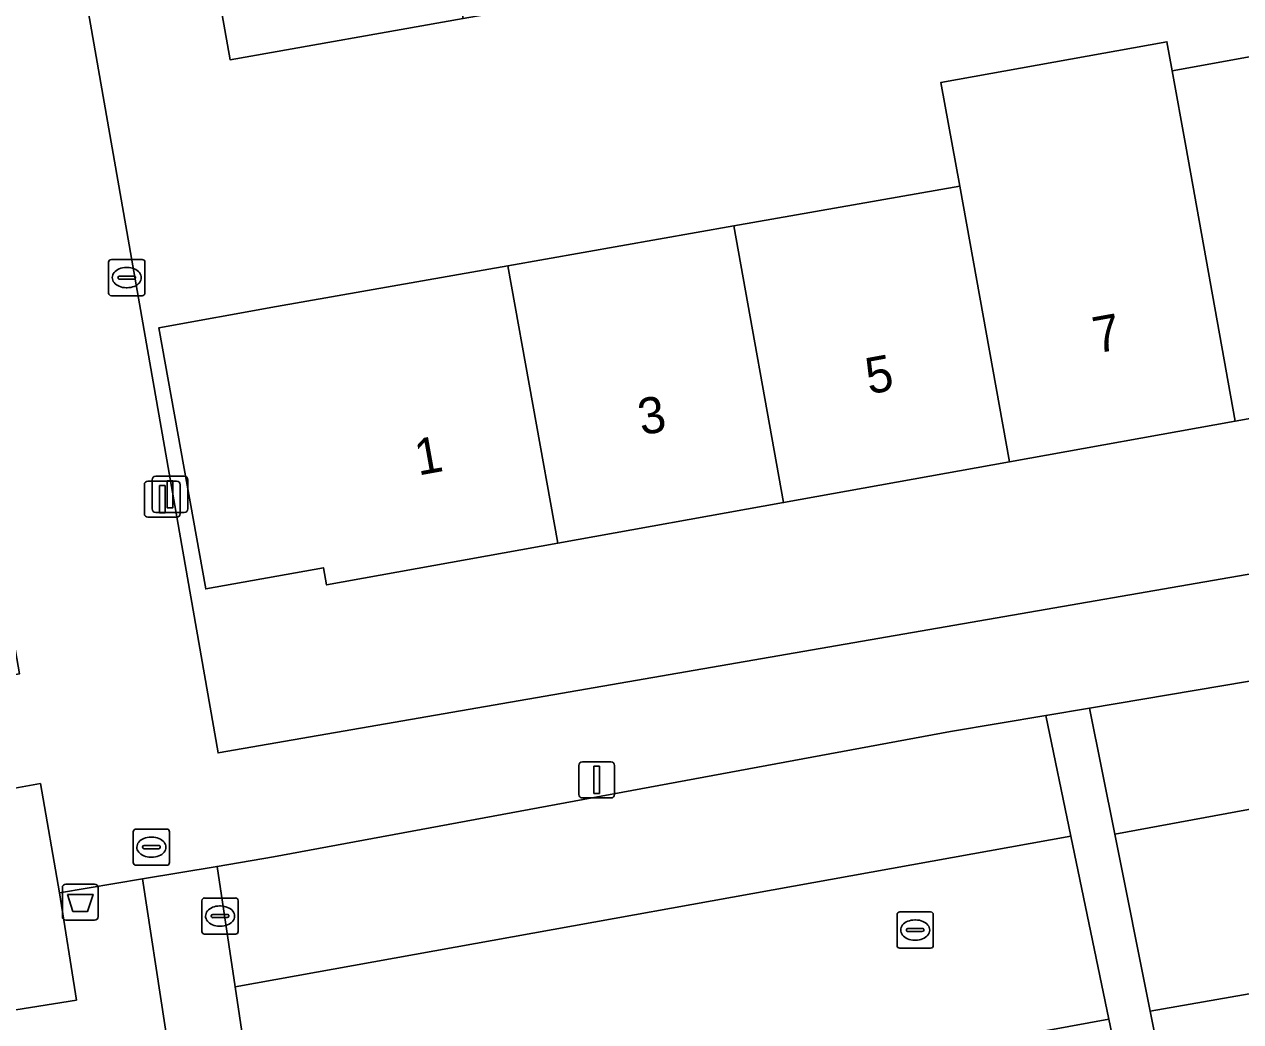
# Model space of a CAD drawing. Extents: x 162879 to 165540, y 384011 to 385181.
# Drawn here: x 164301.67 to 164335.25, y 384254.15 to 384281.7 of the extents above; entities that cross this region are included whole.
import ezdxf

# ---------------------------------------------------------------- set-up
doc = ezdxf.new("R2010")
doc.units = 0
for name, color, linetype in [('IMGEO_Afvalbak', 7, 'Continuous'), ('IMGEO_Erf', 7, 'Continuous'), ('IMGEO_Groenvoorziening', 7, 'Continuous'), ('IMGEO_Kolk', 7, 'Continuous'), ('IMGEO_Lichtmast', 7, 'Continuous'), ('IMGEO_Pand', 7, 'Continuous'), ('IMGEO_Pand_nummerreeks', 7, 'Continuous'), ('IMGEO_Rioolput', 7, 'Continuous'), ('IMGEO_Voetpad_open', 7, 'Continuous')]:
    doc.layers.add(name, color=color, linetype=linetype)

msp = doc.modelspace()

# ---------------------------------------------------------------- linework, layer by layer
at = {"layer": 'IMGEO_Afvalbak'}
for p, q in [((164302.817, 384257.951), (164303.607, 384257.951)), ((164303.607, 384257.951), (164302.817, 384257.951)), ((164302.717, 384257.051), (164302.717, 384257.851)), ((164302.717, 384257.851), (164302.717, 384257.051)), ((164303.707, 384257.851), (164303.707, 384257.051)), ((164303.707, 384257.051), (164303.707, 384257.851)), ((164303.607, 384256.951), (164302.817, 384256.951)), ((164302.817, 384256.951), (164303.607, 384256.951))]:
    msp.add_line(p, q, dxfattribs=at)
msp.add_lwpolyline([(164302.86, 384257.665), (164303.564, 384257.665), (164303.415, 384257.195), (164303.009, 384257.195), (164302.86, 384257.665)], dxfattribs=at)
for centre, start, end in [((164302.817, 384257.851), 90, 180), ((164302.817, 384257.851), 90, 180), ((164303.607, 384257.851), 0, 90), ((164303.607, 384257.851), 360, 90), ((164302.817, 384257.051), 180, 270), ((164302.817, 384257.051), 180, 270), ((164303.607, 384257.051), 270, 0), ((164303.607, 384257.051), 270, 0)]:
    msp.add_arc(centre, 0.1, start, end, dxfattribs=at)
at = {"layer": 'IMGEO_Erf'}
for points in [[(164335.398, 384291.845), (164328.093, 384290.555), (164329.15, 384284.573), (164326.262, 384284.063), (164320.023, 384282.961), (164313.783, 384281.859), (164307.35, 384280.723), (164306.453, 384285.806), (164302.892, 384285.13), (164307.016, 384261.573), (164356.192, 384270.104)], [(164341.337, 384271.862), (164335.102, 384270.739), (164328.866, 384269.615), (164322.631, 384268.491), (164316.395, 384267.367), (164310.011, 384266.217), (164309.926, 384266.689), (164306.678, 384266.104), (164305.378, 384273.317), (164308.626, 384273.902), (164315.014, 384275.029), (164321.254, 384276.131), (164327.493, 384277.232), (164326.976, 384280.098), (164333.212, 384281.222), (164333.357, 384280.421), (164339.591, 384281.545)]]:
    msp.add_lwpolyline(points, dxfattribs=at)
at = {"layer": 'IMGEO_Groenvoorziening'}
for points in [[(164444.217, 384277.406), (164432.573, 384275.206), (164431.046, 384274.979), (164412.171, 384271.782), (164411.664, 384273.084), (164410.216, 384273.782), (164408.706, 384273.531), (164371.45, 384267.278), (164359.532, 384265.161), (164358.499, 384264.978), (164354.911, 384264.392), (164355.011, 384263.622), (164331.775, 384259.327), (164332.753, 384254.442), (164367.352, 384260.503), (164371.077, 384261.125), (164385.399, 384263.612), (164397.49, 384266.196), (164412.669, 384268.778), (164431.26, 384272.662), (164431.272, 384272.664), (164433.193, 384273.044), (164448.321, 384276.269)], [(164448.321, 384276.269), (164433.193, 384273.044), (164431.272, 384272.664), (164431.26, 384272.662), (164412.669, 384268.778), (164397.49, 384266.196), (164385.399, 384263.612), (164371.077, 384261.125), (164367.352, 384260.503), (164332.753, 384254.442), (164333.391, 384251.229), (164332.291, 384250.966), (164331.608, 384254.221), (164308.265, 384249.94), (164308.753, 384246.272), (164306.778, 384245.994), (164298.825, 384244.409), (164297.191, 384244.242), (164295.55, 384244.131), (164274.277, 384245.855), (164270.872, 384246.664), (164271.625, 384245.117)]]:
    msp.add_lwpolyline(points, dxfattribs=at)
for points in [[(164354.911, 384264.392), (164358.499, 384264.978), (164359.532, 384265.161), (164359.516, 384265.186), (164359.415, 384265.343), (164357.5, 384268.334), (164354.177, 384267.752), (164354.364, 384266.743), (164331.078, 384262.811), (164331.775, 384259.327), (164355.011, 384263.622)], [(164329.87, 384262.607), (164327.238, 384262.163), (164308.547, 384258.7), (164306.991, 384258.44), (164307.49, 384255.113), (164330.56, 384259.276)], [(164302.642, 384257.713), (164302.113, 384260.729), (164300.487, 384260.439), (164279.706, 384256.863), (164269.622, 384255.082), (164267.887, 384252.404), (164269.16, 384250), (164269.486, 384249.384), (164303.107, 384254.747)], [(164330.56, 384259.276), (164307.49, 384255.113), (164308.265, 384249.94), (164331.608, 384254.221)], [(164307.49, 384255.113), (164306.991, 384258.44), (164304.926, 384258.095), (164306.778, 384245.994), (164308.753, 384246.272), (164308.265, 384249.94)], [(164304.926, 384258.095), (164302.642, 384257.713), (164303.107, 384254.747), (164269.486, 384249.384), (164270.268, 384247.906), (164270.872, 384246.664), (164274.277, 384245.855), (164295.55, 384244.131), (164297.191, 384244.242), (164298.825, 384244.409), (164306.778, 384245.994)]]:
    msp.add_lwpolyline(points, close=True, dxfattribs=at)
at = {"layer": 'IMGEO_Kolk'}
for p, q in [((164303.995, 384274.279), (164303.995, 384275.131)), ((164304.07, 384275.205), (164304.922, 384275.205)), ((164304.996, 384275.131), (164304.996, 384274.279)), ((164304.254, 384274.699), (164304.254, 384274.711)), ((164304.297, 384274.748), (164304.695, 384274.748)), ((164304.483, 384274.985), (164304.508, 384274.985)), ((164304.738, 384274.711), (164304.738, 384274.699)), ((164304.692, 384274.662), (164304.294, 384274.662)), ((164304.506, 384274.425), (164304.481, 384274.425)), ((164304.922, 384274.205), (164304.07, 384274.205))]:
    msp.add_line(p, q, dxfattribs=at)
for points in [[(164303.995, 384274.279), (164303.995, 384275.131)], [(164304.07, 384275.205), (164304.922, 384275.205)], [(164304.996, 384275.131), (164304.996, 384274.279)], [(164304.922, 384274.205), (164304.07, 384274.205)]]:
    msp.add_lwpolyline(points, dxfattribs=at)
for centre, radius, start, end in [((164304.072, 384275.129), 0.0765, 91.552, 178.448), ((164304.072, 384275.129), 0.0765, 91.552, 178.448), ((164304.92, 384275.129), 0.0765, 1.552, 88.448), ((164304.92, 384275.129), 0.0765, 1.552, 88.448), ((164304.294, 384274.708), 0.0403, 85.8775, 175.7526), ((164304.291, 384274.698), 0.0366, 178.938, 274.7102), ((164304.695, 384274.705), 0.043, 264.8664, 352.4533), ((164304.699, 384274.71), 0.0386, 1.7309, 96.639), ((164304.072, 384274.281), 0.0765, 181.552, 268.448), ((164304.072, 384274.281), 0.0765, 181.552, 268.448), ((164304.92, 384274.281), 0.0765, 271.552, 358.448), ((164304.92, 384274.281), 0.0765, 271.552, 358.448)]:
    msp.add_arc(centre, radius, start, end, dxfattribs=at)
for centre, major_axis, ratio, start_param, end_param in [((164304.482, 384274.705), (-0.387, 0.002), 0.722429, 4.712389, 7.853982), ((164304.507, 384274.705), (-0.39, 0.002), 0.717154, 1.570796, 4.712389)]:
    msp.add_ellipse(centre, major_axis=major_axis, ratio=ratio, start_param=start_param, end_param=end_param, dxfattribs=at)
at = {"layer": 'IMGEO_Lichtmast'}
for p, q in [((164304.982, 384268.184), (164304.982, 384268.984)), ((164304.982, 384268.984), (164304.982, 384268.184)), ((164305.082, 384269.084), (164305.872, 384269.084)), ((164305.872, 384269.084), (164305.082, 384269.084)), ((164305.195, 384268.318), (164305.195, 384269.118)), ((164305.195, 384269.118), (164305.195, 384268.318)), ((164305.295, 384269.218), (164306.085, 384269.218)), ((164306.085, 384269.218), (164305.295, 384269.218)), ((164305.972, 384268.984), (164305.972, 384268.184)), ((164305.972, 384268.184), (164305.972, 384268.984)), ((164306.185, 384269.118), (164306.185, 384268.318)), ((164306.185, 384268.318), (164306.185, 384269.118)), ((164305.872, 384268.084), (164305.082, 384268.084)), ((164305.082, 384268.084), (164305.872, 384268.084)), ((164306.085, 384268.218), (164305.295, 384268.218)), ((164305.295, 384268.218), (164306.085, 384268.218)), ((164317.074, 384261.329), (164317.864, 384261.329)), ((164317.864, 384261.329), (164317.074, 384261.329)), ((164316.974, 384260.429), (164316.974, 384261.229)), ((164316.974, 384261.229), (164316.974, 384260.429)), ((164317.964, 384261.229), (164317.964, 384260.429)), ((164317.964, 384260.429), (164317.964, 384261.229)), ((164317.864, 384260.329), (164317.074, 384260.329)), ((164317.074, 384260.329), (164317.864, 384260.329))]:
    msp.add_line(p, q, dxfattribs=at)
for points in [[(164305.615, 384269.093), (164305.765, 384269.093), (164305.765, 384268.343), (164305.615, 384268.343), (164305.615, 384269.093)], [(164305.402, 384268.959), (164305.552, 384268.959), (164305.552, 384268.209), (164305.402, 384268.209), (164305.402, 384268.959)], [(164317.394, 384261.204), (164317.544, 384261.204), (164317.544, 384260.454), (164317.394, 384260.454), (164317.394, 384261.204)]]:
    msp.add_lwpolyline(points, dxfattribs=at)
for centre, start, end in [((164305.082, 384268.984), 90, 180), ((164305.082, 384268.984), 90, 180), ((164305.295, 384269.118), 90, 180), ((164305.295, 384269.118), 90, 180), ((164305.872, 384268.984), 0, 90), ((164305.872, 384268.984), 360, 90), ((164306.085, 384269.118), 0, 90), ((164306.085, 384269.118), 360, 90), ((164305.295, 384268.318), 180, 270), ((164305.295, 384268.318), 180, 270), ((164306.085, 384268.318), 270, 0), ((164306.085, 384268.318), 270, 0), ((164305.082, 384268.184), 180, 270), ((164305.082, 384268.184), 180, 270), ((164305.872, 384268.184), 270, 0), ((164305.872, 384268.184), 270, 0), ((164317.074, 384261.229), 90, 180), ((164317.074, 384261.229), 90, 180), ((164317.864, 384261.229), 0, 90), ((164317.864, 384261.229), 360, 90), ((164317.074, 384260.429), 180, 270), ((164317.074, 384260.429), 180, 270), ((164317.864, 384260.429), 270, 0), ((164317.864, 384260.429), 270, 0)]:
    msp.add_arc(centre, 0.1, start, end, dxfattribs=at)
at = {"layer": 'IMGEO_Pand'}
for points in [[(164312.705, 384287.837), (164306.294, 384286.705), (164306.453, 384285.806), (164307.35, 384280.723), (164313.783, 384281.859)], [(164339.972, 384279.434), (164339.591, 384281.545), (164333.357, 384280.421), (164333.733, 384278.333), (164335.102, 384270.739), (164341.337, 384271.862)], [(164333.733, 384278.333), (164333.357, 384280.421), (164333.212, 384281.222), (164326.976, 384280.098), (164327.493, 384277.232), (164328.866, 384269.615), (164335.102, 384270.739)], [(164328.866, 384269.615), (164327.493, 384277.232), (164321.254, 384276.131), (164322.631, 384268.491)], [(164322.631, 384268.491), (164321.254, 384276.131), (164315.014, 384275.029), (164316.395, 384267.367)], [(164315.014, 384275.029), (164308.626, 384273.902), (164305.378, 384273.317), (164306.678, 384266.104), (164309.926, 384266.689), (164310.011, 384266.217), (164316.395, 384267.367)]]:
    msp.add_lwpolyline(points, close=True, dxfattribs=at)
at = {"layer": 'IMGEO_Rioolput'}
for p, q in [((164304.675, 384258.545), (164304.675, 384259.397)), ((164304.75, 384259.471), (164305.602, 384259.471)), ((164305.163, 384259.251), (164305.188, 384259.251)), ((164305.676, 384259.397), (164305.676, 384258.545)), ((164304.934, 384258.965), (164304.934, 384258.977)), ((164305.372, 384258.928), (164304.974, 384258.928)), ((164304.977, 384259.014), (164305.375, 384259.014)), ((164305.418, 384258.977), (164305.418, 384258.965)), ((164305.186, 384258.691), (164305.161, 384258.691)), ((164305.602, 384258.471), (164304.75, 384258.471)), ((164306.646, 384257.566), (164307.498, 384257.566)), ((164306.571, 384256.64), (164306.571, 384257.492)), ((164307.059, 384257.346), (164307.084, 384257.346)), ((164307.572, 384257.492), (164307.572, 384256.64)), ((164306.83, 384257.06), (164306.83, 384257.072)), ((164307.268, 384257.023), (164306.87, 384257.023)), ((164306.873, 384257.109), (164307.271, 384257.109)), ((164307.314, 384257.072), (164307.314, 384257.06)), ((164325.763, 384256.254), (164325.763, 384257.106)), ((164325.838, 384257.18), (164326.69, 384257.18)), ((164326.251, 384256.96), (164326.276, 384256.96)), ((164326.764, 384257.106), (164326.764, 384256.254)), ((164307.498, 384256.566), (164306.646, 384256.566)), ((164307.082, 384256.786), (164307.057, 384256.786)), ((164326.022, 384256.674), (164326.022, 384256.686)), ((164326.46, 384256.637), (164326.062, 384256.637)), ((164326.065, 384256.723), (164326.463, 384256.723)), ((164326.506, 384256.686), (164326.506, 384256.674)), ((164326.274, 384256.4), (164326.249, 384256.4)), ((164326.69, 384256.18), (164325.838, 384256.18))]:
    msp.add_line(p, q, dxfattribs=at)
for points in [[(164304.675, 384258.545), (164304.675, 384259.397)], [(164304.75, 384259.471), (164305.602, 384259.471)], [(164305.676, 384259.397), (164305.676, 384258.545)], [(164305.602, 384258.471), (164304.75, 384258.471)], [(164306.646, 384257.566), (164307.498, 384257.566)], [(164306.571, 384256.64), (164306.571, 384257.492)], [(164307.572, 384257.492), (164307.572, 384256.64)], [(164325.763, 384256.254), (164325.763, 384257.106)], [(164325.838, 384257.18), (164326.69, 384257.18)], [(164326.764, 384257.106), (164326.764, 384256.254)], [(164307.498, 384256.566), (164306.646, 384256.566)], [(164326.69, 384256.18), (164325.838, 384256.18)]]:
    msp.add_lwpolyline(points, dxfattribs=at)
for centre, radius, start, end in [((164304.752, 384259.395), 0.0765, 91.552, 178.448), ((164304.752, 384259.395), 0.0765, 91.552, 178.448), ((164305.6, 384259.395), 0.0765, 1.552, 88.448), ((164305.6, 384259.395), 0.0765, 1.552, 88.448), ((164304.974, 384258.974), 0.0403, 85.8775, 175.7526), ((164304.971, 384258.964), 0.0366, 178.938, 274.7102), ((164305.375, 384258.971), 0.043, 264.8664, 352.4533), ((164305.379, 384258.976), 0.0386, 1.7309, 96.639), ((164304.752, 384258.547), 0.0765, 181.552, 268.448), ((164304.752, 384258.547), 0.0765, 181.552, 268.448), ((164305.6, 384258.547), 0.0765, 271.552, 358.448), ((164305.6, 384258.547), 0.0765, 271.552, 358.448), ((164306.648, 384257.49), 0.0765, 91.552, 178.448), ((164306.648, 384257.49), 0.0765, 91.552, 178.448), ((164307.496, 384257.49), 0.0765, 1.552, 88.448), ((164307.496, 384257.49), 0.0765, 1.552, 88.448), ((164306.87, 384257.069), 0.0403, 85.8775, 175.7526), ((164306.867, 384257.059), 0.0366, 178.938, 274.7102), ((164307.271, 384257.066), 0.043, 264.8664, 352.4533), ((164307.275, 384257.071), 0.0386, 1.7309, 96.639), ((164325.84, 384257.104), 0.0765, 91.552, 178.448), ((164325.84, 384257.104), 0.0765, 91.552, 178.448), ((164326.688, 384257.104), 0.0765, 1.552, 88.448), ((164326.688, 384257.104), 0.0765, 1.552, 88.448), ((164306.648, 384256.642), 0.0765, 181.552, 268.448), ((164306.648, 384256.642), 0.0765, 181.552, 268.448), ((164307.496, 384256.642), 0.0765, 271.552, 358.448), ((164307.496, 384256.642), 0.0765, 271.552, 358.448), ((164326.062, 384256.683), 0.0403, 85.8775, 175.7526), ((164326.059, 384256.673), 0.0366, 178.938, 274.7102), ((164326.463, 384256.68), 0.043, 264.8664, 352.4533), ((164326.467, 384256.685), 0.0386, 1.7309, 96.639), ((164325.84, 384256.256), 0.0765, 181.552, 268.448), ((164325.84, 384256.256), 0.0765, 181.552, 268.448), ((164326.688, 384256.256), 0.0765, 271.552, 358.448), ((164326.688, 384256.256), 0.0765, 271.552, 358.448)]:
    msp.add_arc(centre, radius, start, end, dxfattribs=at)
for centre, major_axis, ratio, start_param, end_param in [((164305.162, 384258.971), (-0.387, 0.002), 0.722429, 4.712389, 7.853982), ((164305.187, 384258.971), (-0.39, 0.002), 0.717154, 1.570796, 4.712389), ((164307.058, 384257.066), (-0.387, 0.002), 0.722429, 4.712389, 7.853982), ((164307.083, 384257.066), (-0.39, 0.002), 0.717154, 1.570796, 4.712389), ((164326.25, 384256.68), (-0.387, 0.002), 0.722429, 4.712389, 7.853982), ((164326.275, 384256.68), (-0.39, 0.002), 0.717154, 1.570796, 4.712389)]:
    msp.add_ellipse(centre, major_axis=major_axis, ratio=ratio, start_param=start_param, end_param=end_param, dxfattribs=at)
at = {"layer": 'IMGEO_Voetpad_open'}
for points in [[(164358.04, 384271.68), (164355.977, 384271.342), (164356.192, 384270.104), (164307.016, 384261.573), (164302.892, 384285.13), (164297.965, 384284.257), (164301.53, 384263.755), (164297.909, 384263.112), (164278.541, 384259.775)], [(164279.706, 384256.863), (164300.487, 384260.439), (164302.113, 384260.729), (164302.642, 384257.713), (164304.926, 384258.095), (164306.991, 384258.44), (164308.547, 384258.7), (164327.238, 384262.163), (164329.87, 384262.607), (164331.078, 384262.811), (164354.364, 384266.743), (164354.177, 384267.752), (164357.5, 384268.334), (164357.909, 384268.406), (164370.883, 384270.681), (164372.217, 384270.915), (164409.581, 384277.423)]]:
    msp.add_lwpolyline(points, dxfattribs=at)
msp.add_lwpolyline([(164331.775, 384259.327), (164331.078, 384262.811), (164329.87, 384262.607), (164330.56, 384259.276), (164331.608, 384254.221), (164332.291, 384250.966), (164333.391, 384251.229), (164332.753, 384254.442)], close=True, dxfattribs=at)

# ---------------------------------------------------------------- texts
at = {"layer": 'IMGEO_Pand_nummerreeks'}
for s, rotation, p in [('7', 10.2158, (164331.265, 384272.609)), ('5', 10.2157, (164324.987, 384271.477)), ('3', 10.2157, (164318.709, 384270.346)), ('1', 10.2157, (164312.543, 384269.235))]:
    msp.add_text(s, height=1, rotation=rotation, dxfattribs=at).set_placement(p)

doc.saveas('drawing.dxf')
